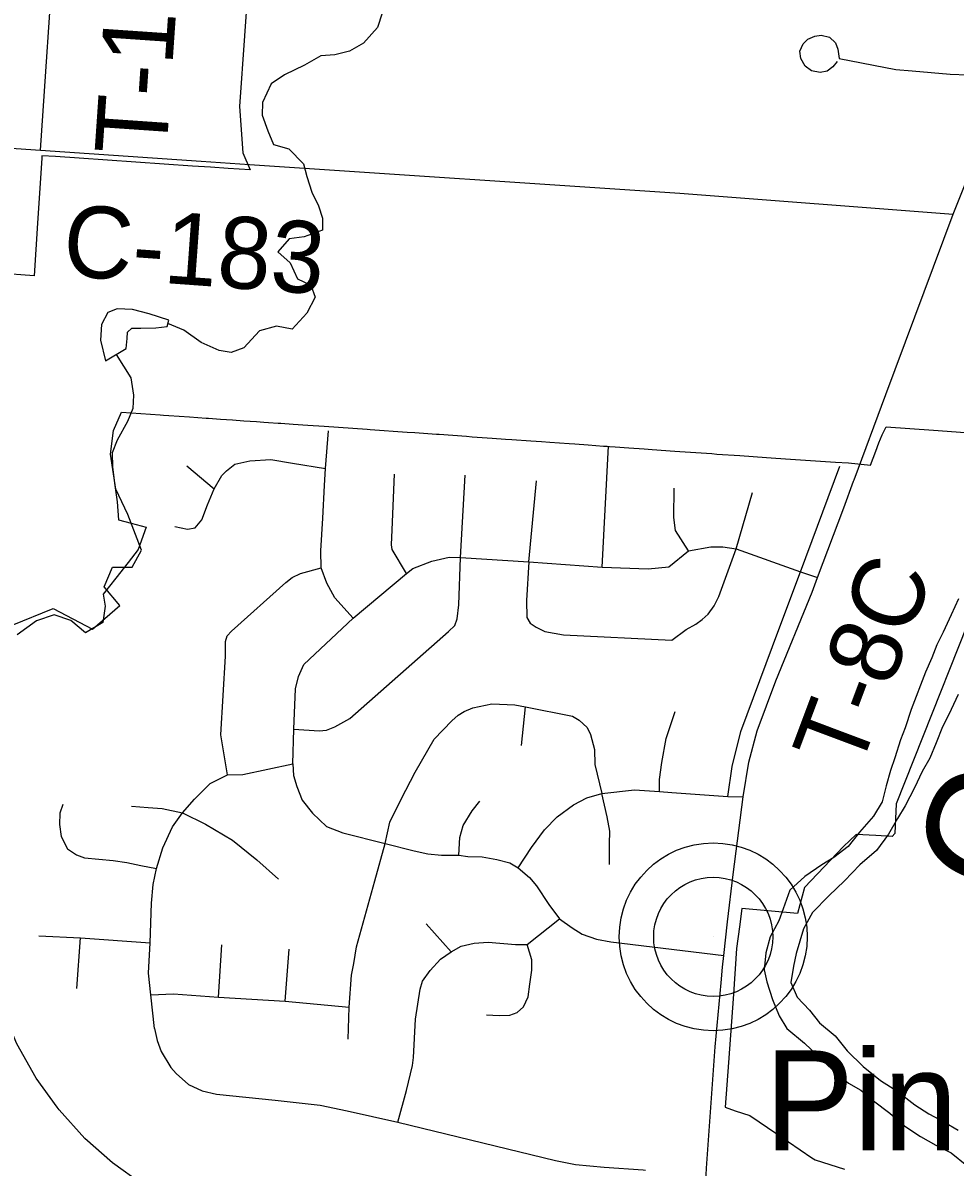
# Model space of a CAD drawing. Extents: x 208586767.6 to 208586821.4, y -134301046.9 to -134301022.9.
# Drawn here: x 208586778.463 to 208586779.201, y -134301025.123 to -134301024.217 of the extents above; entities that cross this region are included whole.
import ezdxf

# ---------------------------------------------------------------- set-up
doc = ezdxf.new("R2010")
doc.units = 0
for name, color, linetype in [('GM_X_City_Street', 7, 'Continuous'), ('GM_X_Corporation', 7, 'Continuous'), ('GM_X_County_Road', 7, 'Continuous'), ('GM_X_County_Road_Text', 7, 'Continuous'), ('GM_X_Interchange_Ramps', 7, 'Continuous'), ('GM_X_Major_River', 7, 'Continuous'), ('GM_X_Major_River_Text', 7, 'Continuous'), ('GM_X_Minor_Lake', 7, 'Continuous'), ('GM_X_Minor_River', 7, 'Continuous'), ('GM_X_Township_Road', 7, 'Continuous'), ('GM_X_Township_Road_Text', 7, 'Continuous'), ('GM_X_Unincorporated', 7, 'Continuous'), ('GM_X_Unincorporated_Location', 7, 'Continuous'), ('GM_X_Unincorporated_Text', 7, 'Continuous')]:
    doc.layers.add(name, color=color, linetype=linetype)

msp = doc.modelspace()

# ---------------------------------------------------------------- linework, layer by layer
at = {"layer": 'GM_X_City_Street'}
msp.add_lwpolyline([(208586779.10749, -134301024.2481), (208586779.10392, -134301024.25237), (208586779.09965, -134301024.2557), (208586779.09394, -134301024.25665), (208586779.08705, -134301024.25546), (208586779.08206, -134301024.25166), (208586779.07874, -134301024.24572), (208586779.07802, -134301024.23978), (208586779.08064, -134301024.23408), (208586779.0842, -134301024.23027), (208586779.0899, -134301024.2279), (208586779.09489, -134301024.22719), (208586779.10131, -134301024.22885), (208586779.10606, -134301024.23336), (208586779.10796, -134301024.23835), (208586779.10915, -134301024.24572), (208586779.15382, -134301024.25451), (208586779.16689, -134301024.25546), (208586779.19707, -134301024.25807), (208586779.21085, -134301024.25855), (208586779.21988, -134301024.25974), (208586779.2418, -134301024.26774)], dxfattribs=at)
at = {"layer": 'GM_X_Corporation'}
for points in [[(208586778.64209, -134301024.17157), (208586778.63402, -134301024.28371), (208586778.63673, -134301024.32024), (208586778.64252, -134301024.33394), (208586778.62509, -134301024.33274), (208586778.61114, -134301024.33179), (208586778.5968, -134301024.3308), (208586778.50716, -134301024.32466), (208586778.48832, -134301024.32337), (208586778.47764, -134301024.32264), (208586778.47751, -134301024.32468), (208586778.47418, -134301024.37592), (208586778.47147, -134301024.41766), (208586778.44292, -134301024.41557)], [(208586778.45422, -134301024.69418), (208586778.48666, -134301024.68115), (208586778.51773, -134301024.69744), (208586778.5395, -134301024.67883), (208586778.527, -134301024.66401), (208586778.53363, -134301024.64829), (208586778.54902, -134301024.64839), (208586778.5566, -134301024.63483), (208586778.54562, -134301024.60658), (208586778.53609, -134301024.58659), (208586778.53212, -134301024.55898), (208586778.53425, -134301024.54018), (208586778.54068, -134301024.52578), (208586778.57145, -134301024.52788), (208586778.57387, -134301024.52805), (208586778.57811, -134301024.52834), (208586778.59465, -134301024.52948), (208586778.60777, -134301024.53038), (208586778.60967, -134301024.53051), (208586778.61906, -134301024.53115), (208586778.62867, -134301024.53181), (208586778.63765, -134301024.53243), (208586778.6477, -134301024.53311), (208586778.65332, -134301024.5335), (208586778.65723, -134301024.53377), (208586778.66485, -134301024.53429), (208586778.66677, -134301024.53442), (208586778.67676, -134301024.53509), (208586778.68827, -134301024.5359), (208586778.70115, -134301024.53678), (208586778.7126, -134301024.53756), (208586778.73534, -134301024.53914), (208586778.73776, -134301024.53931), (208586778.76691, -134301024.54139), (208586778.77302, -134301024.54183), (208586778.79007, -134301024.54305), (208586778.79216, -134301024.5432), (208586778.81399, -134301024.54475), (208586778.81853, -134301024.54508), (208586778.83434, -134301024.54621), (208586778.8448, -134301024.54695), (208586778.84987, -134301024.54732), (208586778.86483, -134301024.54838), (208586778.87321, -134301024.54898), (208586778.88004, -134301024.54947), (208586778.89519, -134301024.55055), (208586778.89964, -134301024.55087), (208586778.91025, -134301024.55162), (208586778.92242, -134301024.55249), (208586778.92535, -134301024.55272), (208586778.9272, -134301024.5529), (208586778.93178, -134301024.55322), (208586778.94245, -134301024.55396), (208586778.95453, -134301024.5548), (208586778.96103, -134301024.55525), (208586778.97898, -134301024.5565), (208586778.98293, -134301024.55677), (208586779.00816, -134301024.55852), (208586779.01228, -134301024.55881), (208586779.03041, -134301024.56007), (208586779.05153, -134301024.56154), (208586779.05532, -134301024.5618), (208586779.06664, -134301024.56259), (208586779.08237, -134301024.56368), (208586779.10603, -134301024.56533), (208586779.11643, -134301024.56572), (208586779.13399, -134301024.5676), (208586779.13816, -134301024.55659), (208586779.14047, -134301024.55003), (208586779.14319, -134301024.54364), (208586779.14639, -134301024.53725), (208586779.18373, -134301024.53983), (208586779.24434, -134301024.54435)], [(208586779.23147, -134301024.64091), (208586779.15423, -134301024.83584), (208586779.15323, -134301024.85934), (208586779.15109, -134301024.86159), (208586779.13816, -134301024.86087), (208586779.12264, -134301024.86001), (208586779.1126, -134301024.86957), (208586779.08169, -134301024.9021), (208586779.07617, -134301024.92254), (208586779.03192, -134301024.91858), (208586779.03, -134301024.93318), (208586779.02768, -134301024.95025), (208586779.02549, -134301024.98641), (208586779.02136, -134301025.04055), (208586779.01867, -134301025.07586), (208586779.02656, -134301025.07869), (208586779.0384, -134301025.08244), (208586779.05973, -134301025.09697), (208586779.08752, -134301025.1159), (208586779.09006, -134301025.11763), (208586779.11339, -134301025.12492)]]:
    msp.add_lwpolyline(points, dxfattribs=at)
at = {"layer": 'GM_X_County_Road'}
for points in [[(208586779.12047, -134301024.58019), (208586779.12082, -134301024.57923), (208586779.14595, -134301024.51171), (208586779.19938, -134301024.36885), (208586779.22651, -134301024.30094), (208586779.2418, -134301024.26774), (208586779.28684, -134301024.1709), (208586779.30049, -134301024.14229), (208586779.31627, -134301024.1104), (208586779.32876, -134301024.08755), (208586779.336, -134301024.07374), (208586779.34044, -134301024.0642), (208586779.34472, -134301024.05236), (208586779.34806, -134301024.04072)], [(208586778.38065, -134301024.31184), (208586778.40718, -134301024.31359), (208586778.47662, -134301024.31827), (208586778.60388, -134301024.32708)], [(208586778.60388, -134301024.32708), (208586778.64206, -134301024.32972), (208586778.9828, -134301024.35235), (208586779.19938, -134301024.36885)], [(208586779.01678, -134301024.9652), (208586779.01771, -134301024.95577), (208586779.02051, -134301024.92914), (208586779.02501, -134301024.89177), (208586779.033, -134301024.83016), (208586779.03744, -134301024.80287), (208586779.04418, -134301024.77805), (208586779.05882, -134301024.73842), (208586779.08759, -134301024.66806), (208586779.09186, -134301024.65655), (208586779.11281, -134301024.6014), (208586779.12047, -134301024.58019)], [(208586778.98752, -134301025.35845), (208586778.9943, -134301025.26173), (208586778.9953, -134301025.24677), (208586778.99583, -134301025.23999), (208586778.99618, -134301025.23494), (208586778.99687, -134301025.22516), (208586778.9982, -134301025.20621), (208586778.99918, -134301025.19215), (208586778.99951, -134301025.18748), (208586779.00359, -134301025.12937), (208586779.00396, -134301025.12431), (208586779.01097, -134301025.02827), (208586779.01558, -134301024.97747), (208586779.01678, -134301024.9652)]]:
    msp.add_lwpolyline(points, dxfattribs=at)
at = {"layer": 'GM_X_Interchange_Ramps'}
msp.add_lwpolyline([(208586778.599, -134301025.15881), (208586778.58213, -134301025.15123), (208586778.56944, -134301025.14427), (208586778.5572, -134301025.13685), (208586778.5336, -134301025.11996), (208586778.51178, -134301025.10066), (208586778.49129, -134301025.07803), (208586778.48975, -134301025.07589), (208586778.47321, -134301025.05299), (208586778.45788, -134301025.02567), (208586778.44564, -134301024.99698), (208586778.43694, -134301024.96739), (208586778.43196, -134301024.93736), (208586778.42939, -134301024.89901), (208586778.42899, -134301024.85724), (208586778.42236, -134301024.85715)], dxfattribs=at)
at = {"layer": 'GM_X_Major_River'}
for points in [[(208586779.20356, -134301024.67358), (208586779.19781, -134301024.68608), (208586779.1913, -134301024.69972), (208586779.18632, -134301024.70995), (208586779.18248, -134301024.72018), (208586779.17749, -134301024.73155), (208586779.16596, -134301024.76111), (208586779.16134, -134301024.77552), (208586779.1575, -134301024.78499), (208586779.15326, -134301024.79939), (208586779.1498, -134301024.80925), (208586779.14632, -134301024.82138), (208586779.14323, -134301024.83428), (208586779.13634, -134301024.84564), (208586779.12528, -134301024.85811), (208586779.11612, -134301024.86946), (208586779.1047, -134301024.87814), (208586779.09519, -134301024.88417), (208586779.08187, -134301024.89322), (208586779.07005, -134301024.90418), (208586779.06467, -134301024.91896), (208586779.06121, -134301024.92844), (208586779.05432, -134301024.94093), (208586779.05085, -134301024.95382), (208586779.04964, -134301024.96711), (208586779.05187, -134301024.97661), (208586779.05635, -134301024.99068), (208586779.0616, -134301025.00361), (208586779.06762, -134301025.01351), (208586779.0816, -134301025.02534), (208586779.09179, -134301025.03488), (208586779.10463, -134301025.04709), (208586779.11634, -134301025.05701), (208586779.12618, -134301025.06237), (208586779.13637, -134301025.07077), (208586779.14922, -134301025.0807), (208586779.16093, -134301025.09101), (208586779.17341, -134301025.09904), (208586779.18551, -134301025.10593), (208586779.19762, -134301025.11206), (208586779.21009, -134301025.12199)], [(208586779.20319, -134301024.74913), (208586779.19591, -134301024.76504), (208586779.19093, -134301024.77489), (208586779.18594, -134301024.7874), (208586779.18095, -134301024.79952), (208586779.17483, -134301024.81013), (208586779.16869, -134301024.823), (208586779.16142, -134301024.8374), (208586779.1553, -134301024.84724), (208586779.14803, -134301024.85974), (208586779.13849, -134301024.8726), (208586779.12553, -134301024.88393), (208586779.11333, -134301024.89678), (208586779.10076, -134301024.9085), (208586779.0878, -134301024.92172), (208586779.08091, -134301024.9346), (208586779.07782, -134301024.94446), (208586779.07512, -134301024.95432), (208586779.0728, -134301024.96418), (208586779.07084, -134301024.97708), (208586779.07571, -134301024.98887), (208586779.08552, -134301024.99916), (208586779.09344, -134301025.00907), (208586779.10591, -134301025.01938), (208586779.11533, -134301025.03119), (208586779.12816, -134301025.04378), (208586779.14177, -134301025.05485), (208586779.15462, -134301025.06289), (208586779.16898, -134301025.07396), (208586779.17994, -134301025.08122), (208586779.19243, -134301025.08774), (208586779.2034, -134301025.09424)]]:
    msp.add_lwpolyline(points, dxfattribs=at)
at = {"layer": 'GM_X_Minor_Lake'}
for points in [[(208586778.54447, -134301024.47535), (208586778.5453, -134301024.46739), (208586778.54535, -134301024.46245), (208586778.5488, -134301024.45907), (208586778.55601, -134301024.45914), (208586778.56777, -134301024.45888), (208586778.57689, -134301024.45783), (208586778.57808, -134301024.45291), (208586778.56257, -134301024.44782), (208586778.54932, -134301024.44427), (208586778.53718, -134301024.44377), (208586778.52994, -134301024.44674), (208586778.52492, -134301024.45618), (208586778.52404, -134301024.46869), (208586778.52805, -134301024.48505)], [(208586778.52805, -134301024.48505), (208586778.54447, -134301024.47535)]]:
    msp.add_lwpolyline(points, dxfattribs=at)
at = {"layer": 'GM_X_Minor_River'}
for points in [[(208586778.74705, -134301024.20976), (208586778.74353, -134301024.22111), (208586778.7324, -134301024.23353), (208586778.72133, -134301024.23987), (208586778.70954, -134301024.24279), (208586778.69853, -134301024.24344), (208586778.68555, -134301024.2509), (208586778.66991, -134301024.25872), (208586778.65922, -134301024.26582), (208586778.65224, -134301024.28056), (208586778.65215, -134301024.29043), (208586778.65658, -134301024.303), (208586778.66103, -134301024.31367), (208586778.67314, -134301024.3172), (208586778.68479, -134301024.32908), (208586778.68735, -134301024.33898), (208586778.6914, -134301024.35154), (208586778.69661, -134301024.36222), (208586778.69993, -134301024.37213), (208586778.69984, -134301024.38161), (208586778.68537, -134301024.38678), (208586778.67358, -134301024.38857), (208586778.66438, -134301024.39872), (208586778.67416, -134301024.40755), (208586778.68011, -134301024.42013), (208586778.69069, -134301024.42517), (208586778.69401, -134301024.43469), (208586778.68744, -134301024.44716), (208586778.67593, -134301024.45995), (208586778.66343, -134301024.45754), (208586778.65011, -134301024.46121), (208586778.63745, -134301024.47475), (208586778.62755, -134301024.47845), (208586778.61808, -134301024.47683), (208586778.60371, -134301024.47062), (208586778.59015, -134301024.46062), (208586778.57749, -134301024.45536)], [(208586778.53646, -134301024.48008), (208586778.54803, -134301024.49853), (208586778.55018, -134301024.51222), (208586778.54969, -134301024.52284), (208586778.54542, -134301024.53305), (208586778.53731, -134301024.54777), (208586778.53341, -134301024.55798), (208586778.53369, -134301024.56899), (208586778.53508, -134301024.58191), (208586778.53721, -134301024.59674), (208586778.53821, -134301024.61079), (208586778.54843, -134301024.61355), (208586778.56017, -134301024.6167), (208586778.55392, -134301024.63448), (208586778.54585, -134301024.64465), (208586778.53625, -134301024.65708), (208586778.52625, -134301024.66988), (208586778.52768, -134301024.67939), (208586778.52604, -134301024.69228), (208586778.51229, -134301024.70049), (208586778.50062, -134301024.69051), (208586778.48738, -134301024.6862), (208586778.4733, -134301024.691), (208586778.45801, -134301024.70185)]]:
    msp.add_lwpolyline(points, dxfattribs=at)
at = {"layer": 'GM_X_Township_Road'}
for p, q in [((208586778.92123, -134301024.64845), (208586778.92645, -134301024.55269)), ((208586778.59248, -134301024.56811), (208586778.61405, -134301024.58645)), ((208586778.80921, -134301024.64062), (208586778.81283, -134301024.57566)), ((208586778.86321, -134301024.64406), (208586778.8694, -134301024.57995)), ((208586779.02741, -134301024.63387), (208586779.0404, -134301024.58915)), ((208586778.85752, -134301024.78957), (208586778.86063, -134301024.75894)), ((208586778.74125, -134301024.8968), (208586778.74947, -134301024.86723)), ((208586778.80174, -134301024.95283), (208586778.78208, -134301024.93069)), ((208586778.50523, -134301024.98196), (208586778.50818, -134301024.94184)), ((208586778.61753, -134301024.9887), (208586778.62023, -134301024.94749)), ((208586778.67032, -134301024.99193), (208586778.67355, -134301024.95072))]:
    msp.add_line(p, q, dxfattribs=at)
for points in [[(208586778.47662, -134301024.31827), (208586778.48785, -134301024.15071), (208586778.49199, -134301024.09803), (208586778.49361, -134301024.07728), (208586778.49476, -134301024.05722), (208586778.49283, -134301024.04281), (208586778.49233, -134301024.04072)], [(208586778.72424, -134301024.68888), (208586778.70953, -134301024.67255), (208586778.70324, -134301024.66105), (208586778.69886, -134301024.64882), (208586778.69868, -134301024.63551), (208586778.7002, -134301024.60968), (208586778.70134, -134301024.58384), (208586778.70238, -134301024.57024), (208586778.70464, -134301024.54055)], [(208586778.58303, -134301024.61624), (208586778.59288, -134301024.6183), (208586778.59898, -134301024.61725), (208586778.6044, -134301024.61087), (208586778.60875, -134301024.59915), (208586778.61405, -134301024.58645), (208586778.62012, -134301024.57576), (208586778.62398, -134301024.57201), (208586778.63051, -134301024.56679), (208586778.64233, -134301024.56431), (208586778.65908, -134301024.56304), (208586778.67614, -134301024.56597), (208586778.70238, -134301024.57024)], [(208586778.76631, -134301024.65335), (208586778.75495, -134301024.63447), (208586778.75463, -134301024.63066), (208586778.75518, -134301024.61889), (208586778.75697, -134301024.57481)], [(208586779.02084, -134301024.82983), (208586779.0242, -134301024.80622), (208586779.0312, -134301024.77854), (208586779.06128, -134301024.69782), (208586779.07855, -134301024.65211), (208586779.10945, -134301024.56843)], [(208586778.98976, -134301024.63535), (208586778.97944, -134301024.61928), (208586778.97807, -134301024.60899), (208586778.97841, -134301024.5858)], [(208586778.67651, -134301024.80407), (208586778.67717, -134301024.77665), (208586778.67843, -134301024.74469), (208586778.68086, -134301024.73484), (208586778.68518, -134301024.72541), (208586778.72424, -134301024.68888), (208586778.76631, -134301024.65335), (208586778.77145, -134301024.64954), (208586778.78636, -134301024.64369), (208586778.80009, -134301024.64048), (208586778.80921, -134301024.64062), (208586778.86321, -134301024.64406), (208586778.92123, -134301024.64845), (208586778.95769, -134301024.64974), (208586778.97407, -134301024.64809), (208586778.98976, -134301024.63535), (208586779.00752, -134301024.63238), (208586779.01705, -134301024.63222), (208586779.02741, -134301024.63387), (208586779.07855, -134301024.65211), (208586779.09186, -134301024.65655)], [(208586778.86321, -134301024.64406), (208586778.86154, -134301024.67488), (208586778.86172, -134301024.68819), (208586778.86432, -134301024.69279), (208586778.86921, -134301024.69591), (208586778.876, -134301024.69943), (208586778.89079, -134301024.70194), (208586778.97663, -134301024.7063), (208586778.98796, -134301024.69765), (208586778.99552, -134301024.69354), (208586779.00061, -134301024.68976), (208586779.00522, -134301024.68565), (208586779.00998, -134301024.67891), (208586779.01377, -134301024.67152), (208586779.02741, -134301024.63387)], [(208586778.67717, -134301024.77665), (208586778.69732, -134301024.77806), (208586778.70303, -134301024.77738), (208586778.70954, -134301024.77482), (208586778.72142, -134301024.76816), (208586778.7996, -134301024.6994), (208586778.80461, -134301024.69454), (208586778.80659, -134301024.68924), (208586778.8079, -134301024.67824), (208586778.80921, -134301024.64062)], [(208586778.62467, -134301024.81287), (208586778.61936, -134301024.78104), (208586778.62294, -134301024.71875), (208586778.62311, -134301024.70734), (208586778.62432, -134301024.7028), (208586778.6278, -134301024.69905), (208586778.67094, -134301024.66055), (208586778.67594, -134301024.65645), (208586778.68245, -134301024.65351), (208586778.69886, -134301024.64882)], [(208586778.74947, -134301024.86723), (208586778.75326, -134301024.85018), (208586778.76211, -134301024.83218), (208586778.77316, -134301024.8107), (208586778.78832, -134301024.78449), (208586778.80235, -134301024.77016), (208586778.80736, -134301024.76568), (208586778.81196, -134301024.7627), (208586778.81885, -134301024.75977), (208586778.8341, -134301024.75658), (208586778.85229, -134301024.7573), (208586778.86063, -134301024.75894), (208586778.89782, -134301024.7663), (208586778.90309, -134301024.76942), (208586778.90946, -134301024.77522), (208586778.91204, -134301024.78097), (208586778.91529, -134301024.7927), (208586778.9156, -134301024.8047), (208586778.92113, -134301024.8276)], [(208586778.96675, -134301024.82589), (208586778.96664, -134301024.8164), (208586778.96873, -134301024.80313), (208586778.97205, -134301024.78416), (208586778.97921, -134301024.76261)], [(208586778.56683, -134301025.0137), (208586778.56394, -134301024.98708), (208586778.56218, -134301024.96988), (208586778.5634, -134301024.94588), (208586778.56447, -134301024.91437), (208586778.56582, -134301024.89955), (208586778.56852, -134301024.88689), (208586778.57337, -134301024.87046), (208586778.58118, -134301024.85403), (208586778.58899, -134301024.84299), (208586778.59846, -134301024.83205), (208586778.6108, -134301024.81969), (208586778.62467, -134301024.81287), (208586778.63676, -134301024.81249), (208586778.67651, -134301024.80407)], [(208586778.67651, -134301024.80407), (208586778.67683, -134301024.81323), (208586778.67968, -134301024.82207), (208586778.68378, -134301024.83281), (208586778.69199, -134301024.84323), (208586778.70305, -134301024.85365), (208586778.71599, -134301024.85871), (208586778.74947, -134301024.86723), (208586778.77253, -134301024.87308), (208586778.78343, -134301024.87545), (208586778.79401, -134301024.87639), (208586778.8079, -134301024.87639), (208586778.81485, -134301024.87734), (208586778.82637, -134301024.87782), (208586778.83806, -134301024.87971), (208586778.84833, -134301024.88255), (208586778.85496, -134301024.8865), (208586778.86381, -134301024.89408), (208586778.86933, -134301024.90055), (208586778.87912, -134301024.91556), (208586778.88749, -134301024.92693), (208586778.8976, -134301024.93403), (208586778.90543, -134301024.939), (208586778.91693, -134301024.94294), (208586778.92828, -134301024.94492), (208586779.01771, -134301024.95577)], [(208586778.85496, -134301024.8865), (208586778.86538, -134301024.87024), (208586778.87565, -134301024.85634), (208586778.8856, -134301024.84607), (208586778.89855, -134301024.8366), (208586778.90913, -134301024.83107), (208586778.92113, -134301024.8276), (208586778.94702, -134301024.82457), (208586778.96675, -134301024.82589), (208586778.97645, -134301024.82671), (208586779.02084, -134301024.82983), (208586779.033, -134301024.83016)], [(208586778.92713, -134301024.88366), (208586778.92713, -134301024.86771), (208586778.92745, -134301024.85744), (208586778.92539, -134301024.84592), (208586778.92113, -134301024.8276)], [(208586778.49418, -134301024.83626), (208586778.49175, -134301024.84326), (208586778.49149, -134301024.85215), (208586778.49284, -134301024.86157), (208586778.49795, -134301024.87127), (208586778.50495, -134301024.87612), (208586778.51142, -134301024.87854), (208586778.53404, -134301024.8807), (208586778.54481, -134301024.88232), (208586778.55613, -134301024.88447), (208586778.56852, -134301024.88689)], [(208586778.54858, -134301024.8376), (208586778.56178, -134301024.83868), (208586778.57282, -134301024.83949), (208586778.58899, -134301024.84299)], [(208586778.8079, -134301024.87639), (208586778.80854, -134301024.86234), (208586778.81122, -134301024.85286), (208586778.81848, -134301024.84134), (208586778.82449, -134301024.8336)], [(208586778.58899, -134301024.84299), (208586778.6073, -134301024.85188), (208586778.62858, -134301024.86454), (208586778.64797, -134301024.88016), (208586778.66494, -134301024.89551)], [(208586778.72023, -134301025.0222), (208586778.72105, -134301024.99668), (208586778.72297, -134301024.97144), (208586778.72462, -134301024.96211), (208586778.72673, -134301024.94904), (208586778.74125, -134301024.8968)], [(208586778.75958, -134301025.08768), (208586778.76637, -134301025.06274), (208586778.77127, -134301025.04284), (208586778.77205, -134301025.03652), (208586778.77363, -134301025.00625), (208586778.77711, -134301024.98251), (208586778.779, -134301024.97604), (208586778.78516, -134301024.96767), (208586778.79337, -134301024.95867), (208586778.80174, -134301024.95283), (208586778.80964, -134301024.94856), (208586778.8199, -134301024.94604), (208586778.83095, -134301024.9454), (208586778.85275, -134301024.94714), (208586778.86207, -134301024.94714), (208586778.88749, -134301024.92693)], [(208586778.47533, -134301024.94022), (208586778.50818, -134301024.94184), (208586778.5634, -134301024.94588)], [(208586778.82985, -134301025.00272), (208586778.8398, -134301025.00336), (208586778.84817, -134301025.0032), (208586778.85417, -134301025.00099), (208586778.85906, -134301024.99641), (208586778.8627, -134301024.98868), (208586778.86412, -134301024.97857), (208586778.86554, -134301024.96751), (208586778.86554, -134301024.9593), (208586778.86207, -134301024.94714)], [(208586778.56394, -134301024.98708), (208586778.58198, -134301024.98628), (208586778.61753, -134301024.9887), (208586778.67032, -134301024.99193), (208586778.72105, -134301024.99668)], [(208586778.56683, -134301025.0137), (208586778.56889, -134301025.02316), (208586778.57205, -134301025.0318), (208586778.57987, -134301025.04457), (208586778.58397, -134301025.04918), (208586778.59386, -134301025.05788), (208586778.6047, -134301025.06309), (208586778.61595, -134301025.0657), (208586778.66233, -134301025.07036), (208586778.69815, -134301025.07426), (208586778.71931, -134301025.07869), (208586778.75958, -134301025.08768), (208586778.88434, -134301025.11823), (208586778.90017, -134301025.1212), (208586778.92293, -134301025.12343), (208586778.95385, -134301025.12565), (208586778.95577, -134301025.12579)]]:
    msp.add_lwpolyline(points, dxfattribs=at)
at = {"layer": 'GM_X_Unincorporated'}
for radius in [0.0744, 0.04716]:
    msp.add_circle((208586779.00931, -134301024.94105), radius, dxfattribs=at)
at = {"layer": 'GM_X_Unincorporated_Location'}
msp.add_line((208586779.00931, -134301024.94105), (208586779.00931, -134301024.94105), dxfattribs=at)

# ---------------------------------------------------------------- texts
at = {"layer": 'GM_X_County_Road_Text'}
msp.add_text('C-183', height=0.056818, rotation=355.87541, dxfattribs=at).set_placement((208586778.4931, -134301024.41756))
at = {"layer": 'GM_X_Major_River_Text'}
msp.add_text('Creek', height=0.094695, rotation=70.0013, dxfattribs=at).set_placement((208586779.25435, -134301024.91656))
at = {"layer": 'GM_X_Township_Road_Text'}
for s, rotation, p in [('T-184', 86.07407, (208586778.57608, -134301024.32334)), ('T-8C', 69.41395, (208586779.12434, -134301024.81198))]:
    msp.add_text(s, height=0.056818, rotation=rotation, dxfattribs=at).set_placement(p)
at = {"layer": 'GM_X_Unincorporated_Text'}
msp.add_text('Pinhook', height=0.078977, rotation=0.00001, dxfattribs=at).set_placement((208586779.0502, -134301025.10997))

doc.saveas('drawing.dxf')
